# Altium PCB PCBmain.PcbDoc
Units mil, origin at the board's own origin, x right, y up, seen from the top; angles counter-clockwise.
Board outline 3224.41 x 4480.32 mil, 2 copper layers (Top Layer, Bottom Layer); 64 components, 75 nets, 222 pads, 65 vias.
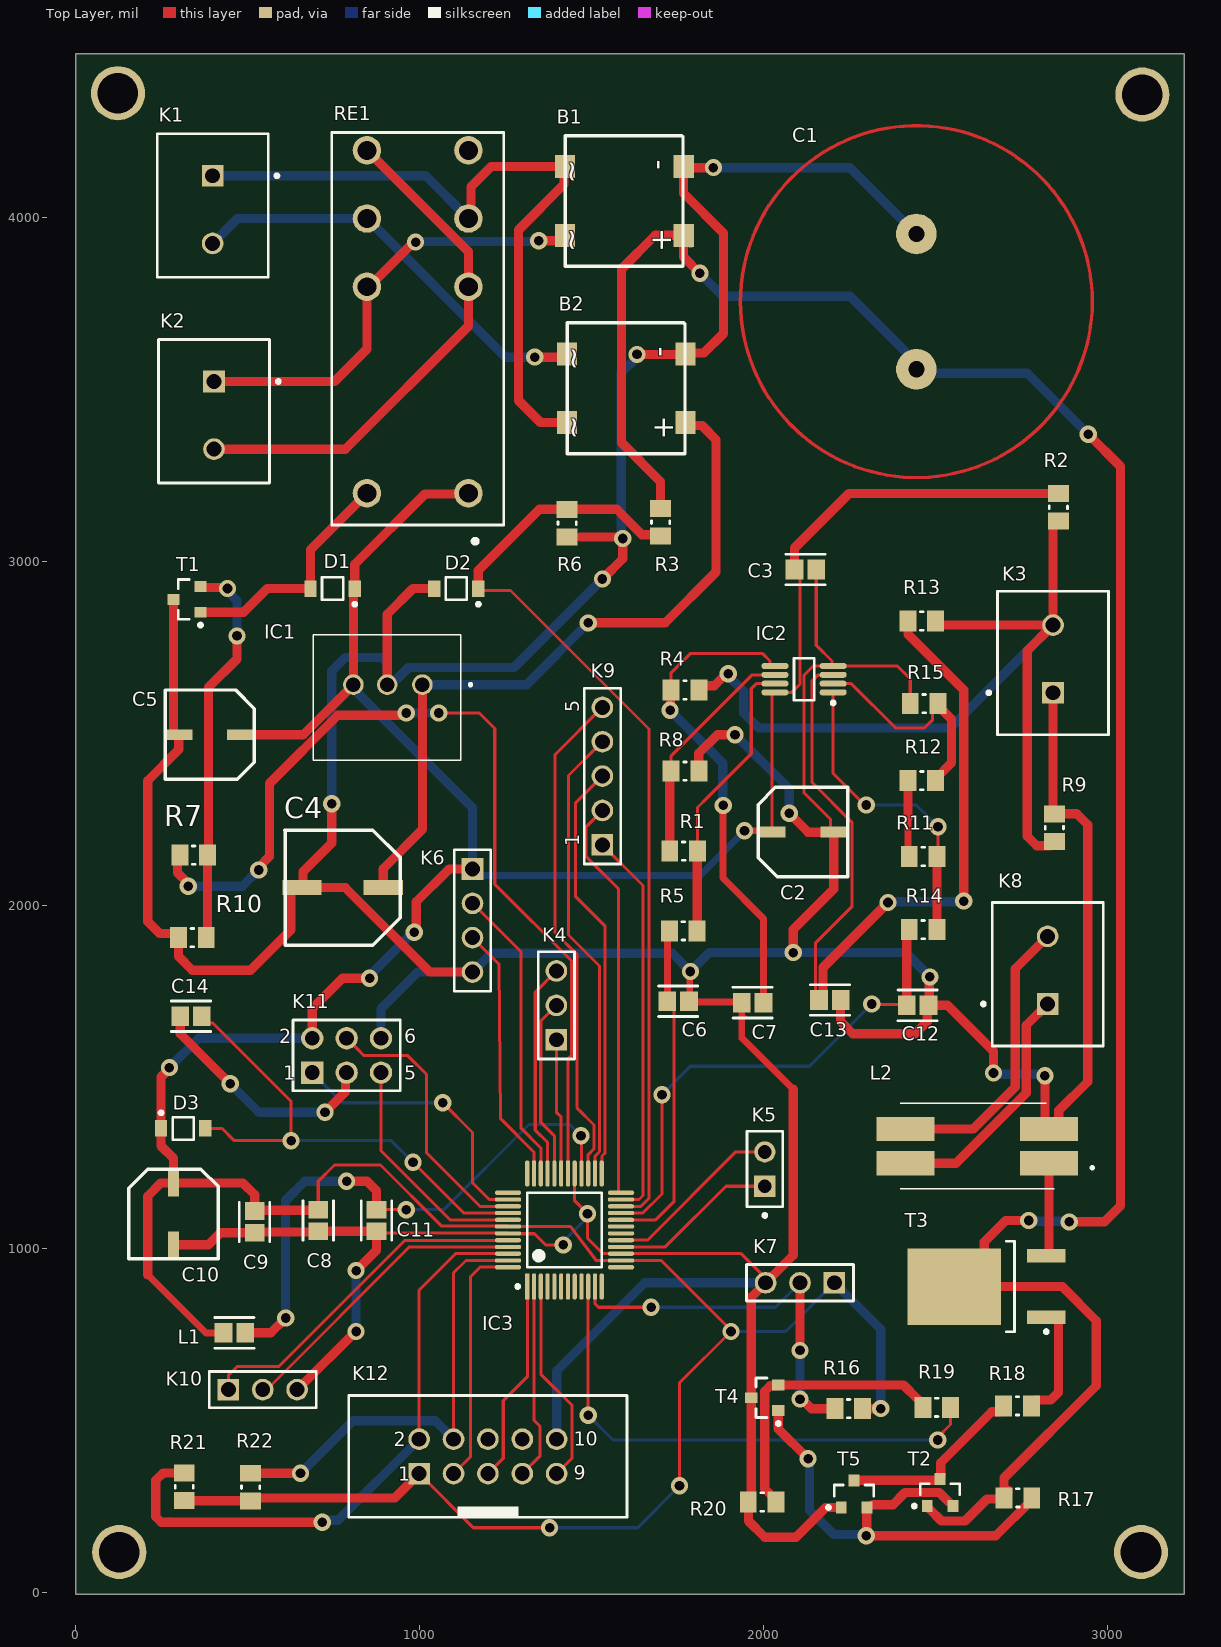
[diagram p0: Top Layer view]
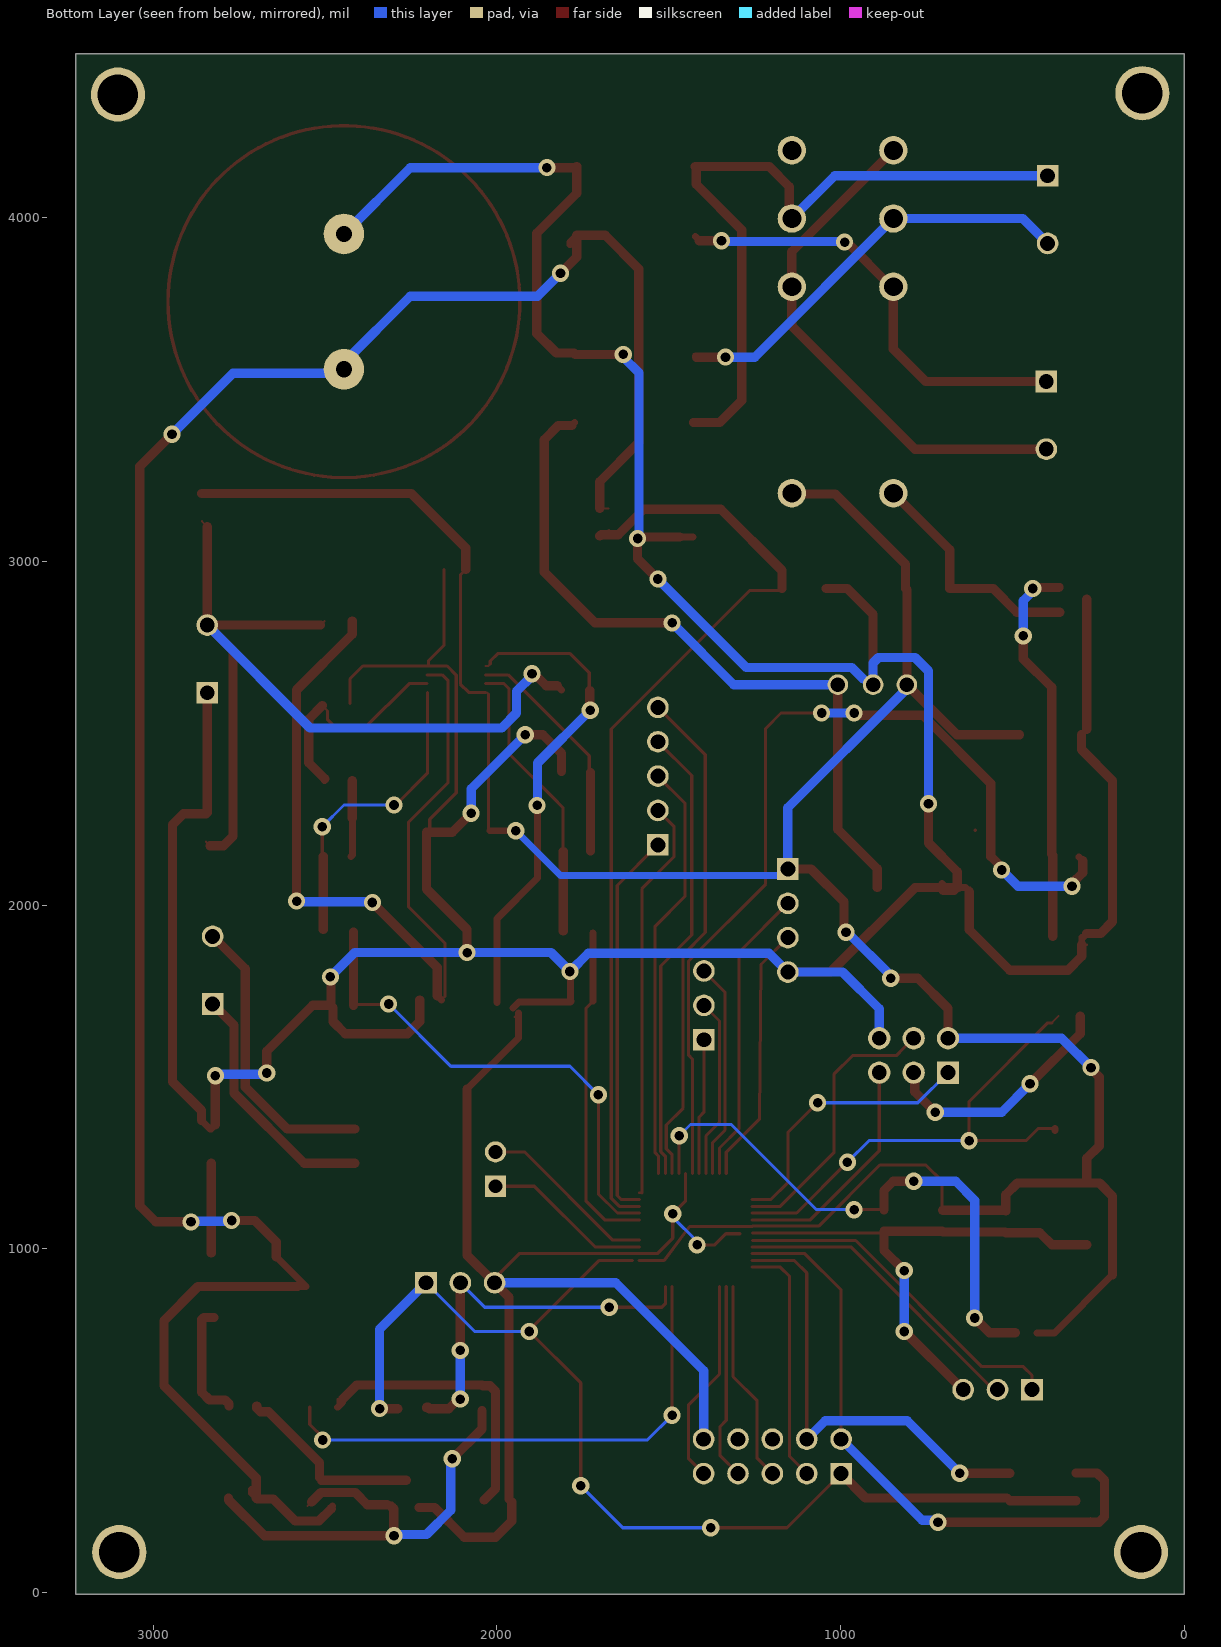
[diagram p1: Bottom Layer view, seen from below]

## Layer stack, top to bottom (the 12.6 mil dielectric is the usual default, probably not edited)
Top Solder: solder mask 0.4, Solder Resist, Dk 3.5
Top Layer: signal copper 1.4
Dielectric 1: dielectric 12.6, FR-4, Dk 4.8
Bottom Layer: signal copper 1.4
Bottom Solder: solder mask 0.4, Solder Resist, Dk 3.5

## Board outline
0,-3.94 3224.41,-3.94 3224.41,4476.38 0,4476.38

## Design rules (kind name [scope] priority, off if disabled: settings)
Clearance [All] p1: gap=2 ignorepadtopadclearanceinfootprint=TRUE except(0: Arc-Hole Track-Hole SMDPad-Hole THPad-Hole Via-Hole Fill-Hole Poly-Hole Region-Hole Text-Hole)
HoleSize [All] p1: absolutevalues=TRUE maxlimit=157.48 minlimit=0.98 maxpercent=80.000 minpercent=20.000
MinimumSolderMaskSliver [All] p1: minsoldermaskwidth=2
PolygonConnect [All] p1: connectstyle=Relief reliefconductorwidth=10 reliefentries=4 polygonreliefangle="90 Angle" airgapwidth=10
RoutingVias [All] p1: holewidth=28 width=50 viastyle="Through Hole" minholewidth=28 minwidth=50 maxholewidth=28 maxwidth=50
SilkToSilkClearance [All] p1: silktosilkclearance=2
SilkToSolderMaskClearance [IsPad] p1: minsilkscreentomaskgap=0 clearancetoexposedcopper=TRUE
SolderMaskExpansion [All] p1: expansion=4 istentingtop=FALSE
Width [All] p1: maxlimit=27 minlimit=6 preferedwidth=20 minimp=50.000000 maximp=50.000000 favimp=50.000000
26 further rules are at their usual default settings.

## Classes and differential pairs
component class voeding: B1 B2 C1 C4 C5 D1 D2 IC1 K1 K2 R3 R6 R7 R10 RE1 T1
component class thermokoppel: C2 C3 C6 C7 C12 C13 IC2 K3 R1 R2 R4 R5 R8 R9 R11 R12 R13 R14 R15
component class PWM: K8 L2 R17 R18 R19 R20 T2 T3 T4 T5
component class CPU: C8 C9 C10 C11 C14 D3 IC3 K4 K5 K6 K7 K9 K10 K11 L1 R16 R21 R22

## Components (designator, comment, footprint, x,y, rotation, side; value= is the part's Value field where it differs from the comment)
B1 "Bridge Rectifier" "ttf (bridge rectifier)" 1592.72,4048.82 r270 top
B2 "Bridge Rectifier" "ttf (bridge rectifier)" 1598.43,3503.94 r270 top
C1 "4700µ" C470µ 2444.88,3755.91 r270 top
C2 "10µ" "CE_D6,3_L4,5 (capacitor electrolytic)" 2114.72,2212.6 r180 top
C3 "100n" "CC_0805_L (choke/capacitor)" 2122.05,2976.38 r0 top value="0.22 μF"
C4 "100µ" CE_D8_L10 775.59,2051.18 r0 top
C5 "10µ" "CE_D6,3_L4,5 (capacitor electrolytic)" 389.21,2496.06 r0 top
C6 "10n" "CC_0805_L (choke/capacitor)" 1751.97,1720.47 r180 top value="0.22 μF"
C7 "10n" "CC_0805_L (choke/capacitor)" 1968.53,1716.53 r0 top value="0.22 μF"
C8 "100n" "CC_0805_L (choke/capacitor)" 704.72,1082.68 r270 top value="0.22 μF"
C9 "100n" "CC_0805_L (choke/capacitor)" 519.68,1078.74 r270 top value="0.22 μF"
C10 "10µ" "CE_D6,3_L4,5 (capacitor electrolytic)" 283.46,1101.81 r90 top
C11 "100n" "CC_0805_L (choke/capacitor)" 874.02,1082.68 r270 top value="0.22 μF"
C12 "10n" "CC_0805_L (choke/capacitor)" 2448.82,1708.66 r180 top value="0.22 μF"
C13 "10n" "CC_0805_L (choke/capacitor)" 2192.95,1724.41 r180 top value="0.22 μF"
C14 "100n" "CC_0805_L (choke/capacitor)" 334.68,1677.16 r180 top value="0.22 μF"
D1 "Diode" "SOD-123FL (diode)" 746.65,2921.26 r180 top value=15pF
D2 "5V1" "SOD-123FL (diode)" 1106.3,2921.26 r180 top value=15pF
D3 "Diode" "SOD-123FL (diode)" 311.95,1350.39 r0 top value=15pF
IC1 "OKI-78SR-5/1.5-W36-C" "OKI78SR515W36C ( DC/DC Converter)" 1007.87,2641.73 r180 top
IC2 "" "MSOP_8_L (dual opamp)" 2118.11,2657.48 r180 top
IC3 "ATMEGA4809" "TQFP_48_L (atmega)" 1421.26,1055.12 r90 top
K1 "282836-2" terminal_block 397.64,4023.62 r270 top
K2 "282836-2" terminal_block 401.57,3425.2 r270 top
K3 "" terminal_block 2842.52,2716.54 r90 top
K4 "61300311121" "pin header 1x3" 1397.64,1708.66 r90 top
K5 "M20-9990246" "pin header 1x2" 2003.94,1232.28 r90 top
K6 "61300411121" "pin header 1x4" 1153.54,1955.51 r270 top
K7 "61300311121" "pin header 1x3" 2106.3,901.57 r180 top
K8 "282836-2" terminal_block 2826.77,1811.03 r90 top
K9 "61300511121" "pin header 1x5" 1531.5,2375.59 r90 top
K10 "61300311121" "pin header 1x3" 543.31,590.55 r0 top
K11 "61300621121" "pin header 2x6" 787.4,1562.99 r0 top
K12 "61201021621" "box header 10-pin" 1198.42,396.46 r0 top
L1 "10µH" "CC_0805_L (choke/capacitor)" 460.63,755.91 r180 top
L2 "" "2545 (common mode choke)" 2622.05,1299.21 r90 top
R1 "18k" R_0805_L 1767.72,2157.48 r180 top
R2 "1M" R_0805_L 2858.27,3157.48 r270 top
R3 "68k" R_0805_L 1700.79,3114.17 r90 top
R4 "5k6" R_0805_L 1771.65,2625.98 r0 top
R5 "5k6" R_0805_L 1766.73,1925.2 r0 top
R6 "10k" R_0805_L 1429.13,3111.22 r90 top
R7 "10k" R_0805_L 342.52,2145.67 r0 top
R8 "100" R_0805_L 1771.65,2389.76 r180 top
R9 "10M" R_0805_L 2846.46,2225.4 r90 top
R10 "4k7" R_0805_L 338.58,1905.51 r0 top
R11 "18k" R_0805_L 2464.57,2141.73 r0 top
R12 "18k" R_0805_L 2460.63,2362.2 r0 top
R13 "5k6" R_0805_L 2460.63,2826.77 r0 top
R14 "5k6" R_0805_L 2464.57,1929.13 r180 top
R15 "100" R_0805_L 2467.52,2586.61 r0 top
R16 "4k7" R_0805_L 2248.03,535.43 r0 top
R17 "4k7" R_0805_L 2740.16,275.59 r180 top
R18 "100" R_0805_L 2739.17,543.31 r180 top
R19 "10k" R_0805_L 2503.94,539.37 r0 top
R20 "4k7" R_0805_L 1996.06,263.78 r0 top
R21 "4k7" R_0805_L 314.96,308.07 r270 top
R22 "4k7" R_0805_L 507.87,307.09 r270 top
RE1 "Relay general purpose" "RT42 (relay general p)" 994.09,3198.43 r90 top
T1 "" "SOT_23 (transistors)" 322.83,2889.76 r180 top
T2 "" "SOT_23 (transistors)" 2513.78,291.34 r90 top
T3 "" "TO_252 (mosfet)" 2649.6,890.55 r180 top
T4 "" "SOT_23 (transistors)" 2003.94,566.93 r180 top
T5 "" "SOT_23 (transistors)" 2263.78,287.4 r90 top

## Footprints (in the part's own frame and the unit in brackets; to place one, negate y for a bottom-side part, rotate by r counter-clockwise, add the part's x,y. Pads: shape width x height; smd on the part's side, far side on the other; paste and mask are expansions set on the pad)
"2545 (common mode choke)" [mm]
  rect 1.78x4.27 smd: 1(-1.27,-5.305) 2(1.27,-5.305) 3(1.27,5.305) 4(-1.27,5.305)
  silkscreen extent -3.15,-8.6 3.15,5.69, body extent -3.15,-7.26 3.15,7.26, height 9.6
"box header 10-pin" [mm] "10 pins, straight, gold plating"
  rect 1.6x1.6 hole 1.1: 1(-5.08,-1.27)
  round 1.6 hole 1.1: 2(-5.08,1.27) 3(-2.54,-1.27) 4(-2.54,1.27) 5(0,-1.27) 6(0,1.27) 7(2.54,-1.27) 8(2.54,1.27) 9(5.08,-1.27) 10(5.08,1.27)
  silkscreen extent -10.28,-4.5 10.28,4.5, body extent -10.18,-4.42 10.18,4.75, height 9.13
C470µ [mm]
  round 3 hole 1.2: 1(-5,0) 2(5,0)
  Top Layer circle w0.254: c0,0 r13
"CC_0805_L (choke/capacitor)" [mil]
  rect 51.36x57.33 smd paste+0 mask+0: 1(-31.53,0) 2(31.53,0)
  silkscreen extent -57,-44 57,44, body extent -67,-39 67,39, height 10
"CE_D6,3_L4,5 (capacitor electrolytic)" [mm]
  rect 2x0.8 smd: 1(-2.286,0) 2(2.286,0)
  silkscreen extent -3.3,-3.3 3.3,3.3
CE_D8_L10 [mm]
  rect 2.9x1.1 smd: 1(-3,0) 2(3,0)
  Top Layer lines w0.254: -4.259,4.25 -4.25,4.241
  silkscreen extent -4.26,-4.25 4.25,4.25
"MSOP_8_L (dual opamp)" [mm] "TSOP, 8-Leads, Body 3x3mm, Pitch 0.65mm, IPC Low Density"
  oval 2x0.45 smd: 1(-2.15,0.975) 2(-2.15,0.325) 3(-2.15,-0.325) 4(-2.15,-0.975) 5(2.15,-0.975) 6(2.15,-0.325) 7(2.15,0.325) 8(2.15,0.975)
  silkscreen extent -2.27,-1.55 0.75,1.87, body extent -1.55,-1.55 1.55,1.55, height 1.1
"OKI78SR515W36C ( DC/DC Converter)" [mm]
  round 1.519 hole 1.08: 1(0,0) 2(2.6,0) 3(5.1,0)
  silkscreen extent -3.6,-3.7 8.05,5.6, body extent -2.85,-3.7 8.05,5.6, height 16.6
"pin header 1x2" [mm]
  rect 1.57x1.57 hole 1.02 paste-1000 mask+0: 1(-1.27,0)
  round 1.57 hole 1.02 paste-1000 mask+0: 2(1.27,0)
  silkscreen extent -3.55,-1.32 2.79,1.32, body extent -2.89,-1.42 2.89,1.42, height 0.25
"pin header 1x3" [mm] "Pin Header, pitch 2.54 mm, THT, Vertical, single row, 3p"
  rect 1.6x1.6 hole 1.1: 1(-2.54,0)
  round 1.6 hole 1.1: 2(0,0) 3(2.54,0)
  silkscreen extent -3.96,-1.34 3.96,1.34, body extent -3.81,-1.27 3.81,1.27, height 8.57
"pin header 1x4" [mm] "Pin Header, pitch 2.54 mm, THT, Vertical, single row, 4p"
  rect 1.6x1.6 hole 1.1: 1(-3.81,0)
  round 1.6 hole 1.1: 2(-1.27,0) 3(1.27,0) 4(3.81,0)
  silkscreen extent -5.23,-1.35 5.23,1.35, body extent -5.08,-1.27 5.08,1.27, height 8.57
"pin header 1x5" [mm] "Pin Header, pitch 2.54 mm, THT, Vertical, single row, 5p"
  rect 1.6x1.6 hole 1.1: 1(-5.08,0)
  round 1.6 hole 1.1: 2(-2.54,0) 3(0,0) 4(2.54,0) 5(5.08,0)
  silkscreen extent -6.5,-1.34 6.5,1.35, body extent -6.35,-1.27 6.35,1.27, height 8.57
"pin header 2x6" [mm] "Pin Header, pitch 2.54 mm, THT, Vertical, dual row, 6p"
  rect 1.65x1.65 hole 1.1: 1(-2.54,-1.27)
  round 1.65 hole 1.1: 2(-2.54,1.27) 3(0,-1.27) 4(0,1.27) 5(2.54,-1.27) 6(2.54,1.27)
  silkscreen extent -3.96,-2.62 3.96,2.61, body extent -3.81,-2.54 3.81,2.54, height 8.59
R_0805_L [mm] "Chip Resistor, 2-Leads, Body 2.00x1.25mm, IPC Low Density"
  rect 1.25x1.55 smd: 1(-1.025,0) 2(1.025,0)
  silkscreen extent -0.1,-0.68 0.1,0.67, body extent -1.1,-0.72 1.1,0.72, height 0.5
"RT42 (relay general p)" [mm]
  round 2.1 hole 1.4: 1(0,-3.75) 2(15.26,-3.75) 3(20.3,-3.75) 4(25.34,-3.75) 5(25.34,3.75) 6(20.3,3.75) 7(15.26,3.75) 8(0,3.75)
  silkscreen extent -3.67,-6.35 26.65,6.35, body extent -2.21,-6.35 26.79,6.35, height 15.86
"SOD-123FL (diode)" [mm] "SOD, 2-Leads, Body 2.7x1.65mm"
  rect 0.91x1.22 smd: 1(-1.635,0) 2(1.635,0)
  silkscreen extent -1.76,-0.83 0.78,1.28, body extent -1.35,-0.82 1.35,0.82, height 1
"SOT_23 (transistors)" [mm] "SOT23, 3-Leads, Body 2.92x1.3mm, Pitch 0.95mm"
  rect 0.9x0.8 smd: 1(-1,0.95) 2(-1,-0.95) 3(1,0)
  silkscreen extent -1.13,-1.46 0.65,2.02, body extent -0.65,-1.46 0.65,1.46, height 1.11
terminal_block [mm] "Female Header, Pitch 5mm, 1 x 2 Position, Height 10mm"
  rect 1.6x1.6 hole 1.1: 1(-2.5,0)
  round 1.6 hole 1.1: 2(2.5,0)
  silkscreen extent -5.6,-4.1 5,4.88, body extent -5.6,-4.1 5,4.1, height 10
"TO_252 (mosfet)" [mm] "DPAK, 3-Leads, Body 6.5x6.12mm, Pitch 2.28mm, IPC Low Density"
  rect 2.85x1 smd: 1(-4.4,2.28) 3(-4.4,-2.28)
  rect 6.9x5.65 smd: 2(2.4,0)
  silkscreen extent -4.53,-3.35 -1.45,3.45, body extent -2.05,-3.32 4.17,3.32, height 2.35
"TQFP_48_L (atmega)" [mm]
  rect 1.955x0.312 smd paste+0 mask+0: 1(-4.175,2.75)
  rrect100% 1.955x0.312 smd paste+0 mask+0: 2(-4.175,2.25) 3(-4.175,1.75) 4(-4.175,1.25) 5(-4.175,0.75) 6(-4.175,0.25) 7(-4.175,-0.25) 8(-4.175,-0.75) 9(-4.175,-1.25) 10(-4.175,-1.75) 11(-4.175,-2.25) 12(-4.175,-2.75) 25(4.176,-2.75) 26(4.176,-2.25) 27(4.176,-1.75) 28(4.176,-1.25) 29(4.176,-0.75) 30(4.176,-0.25) 31(4.176,0.25) 32(4.176,0.75) 33(4.176,1.25) 34(4.176,1.75) 35(4.176,2.25) 36(4.176,2.75)
  rrect100% 0.312x1.955 smd paste+0 mask+0: 13(-2.75,-4.175) 14(-2.25,-4.175) 15(-1.75,-4.175) 16(-1.25,-4.175) 17(-0.75,-4.175) 18(-0.25,-4.175) 19(0.25,-4.175) 20(0.75,-4.175) 21(1.25,-4.175) 22(1.75,-4.175) 23(2.25,-4.175) 24(2.75,-4.175) 37(2.75,4.175) 38(2.25,4.175) 39(1.75,4.175) 40(1.25,4.175) 41(0.75,4.175) 42(0.25,4.175) 43(-0.25,4.175) 44(-0.75,4.175) 45(-1.25,4.175) 46(-1.75,4.175) 47(-2.25,4.175) 48(-2.75,4.175)
  silkscreen extent -4.3,-2.75 2.75,3.58, body extent -5.65,-5.65 5.65,5.65, height 0.25
"ttf (bridge rectifier)" [mm]
  rect 1.7x1.5 smd: 1(2.54,4.445) 2(-2.54,4.445) 3(-2.54,-4.318) 4(2.54,-4.318)
  silkscreen extent -4.83,-4.3 4.83,4.4

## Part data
B1 B2: Average Rectified Current-Max=0.8A, Forward Voltage=1V, Manufacturer="Diodes Inc", Package Description="4-Pin Small Outline Integrated Circuit, Body 4.7 x 3.8 mm, Pitch 2.5 mm", Package Reference=MiniDIP-4, Package Version=05/2016, Peak Current-Max=30A, Reverse Current-Max=5µA, Reverse Voltage-Max [Vrrm]=600V
C1 C2 C4 C5 C10: library part "Capacitor (electrolytic)", Manufacturer=Panasonic, Max Operating Temperature="105 degC", Min Operating Temperature="-55 degC", Package Quantity=500, Voltage Rating="25 V"
C3 C6 C7 C8 C9 C11 C12 C13 C14: library part "Capacitor (ceramic)", Capacitance="0.22 μF", Manufacturer=KEMET, Manufacturer Part Number=C0805C224K5RACTU, Package=C0805C-DN, Temperature="-55°C to +125°C", Temperature Characteristic=X7R, Temperature Coefficient=30ppm/°C, Temperature Range High=+125°C, Temperature Range Low=-55°C, Tolerance=0.1, Voltage Rating="50 V"
D1 D3: Capacitance=15pF, Forward Current=1A, Manufacturer=Diotec, Manufacturer Part Number=1N4007, Max Junction Temp=+175°C, Max Repetitive Reverse Voltage=1000V, Max Surge Forward Current=27A, Peak Reverse Current=5uA, Temperature="-50°C to +175°C", Temperature Range Low=-50°C
D2: library part "Zener diode", Capacitance=15pF, Forward Current=1A, Manufacturer=Diotec, Manufacturer Part Number=1N4007, Max Junction Temp=+175°C, Max Repetitive Reverse Voltage=1000V, Max Surge Forward Current=27A, Peak Reverse Current=5uA, Temperature="-50°C to +175°C", Temperature Range Low=-50°C
IC1: library part "DC/DC Converter", Current - Output (Max)=1.5A, Manufacturer=Murata, Operating Temperature=-40degC~85degC, Package / Case=3-SIPModule, Power (Watts) - Manufacture Series=8W, Voltage - Input (Max)=36V, Voltage - Input (Min)=7V, Voltage - Isolation=-, Voltage - Output 1=5V
IC2: library part "Dual Opamp", Case/Package=PDIP, Input Bias Current=1pA, Input Offset Voltage (Vos)=4.5mV, Max Operating Temperature=125°C, Max Supply Voltage=6V, Min Operating Temperature=-40°C, Min Supply Voltage=1.8V, Nominal Supply Current=100uA, Operating Supply Voltage=5.5V, Output Current=23mA, Package Quantity=60, Power Supply Rejection Ratio (PSRR)=86dB, Voltage Gain=112dB
IC3: Case/Package=TQFP, Max Operating Temperature=85°C, Min Operating Temperature=-40°C
K1 K2 K3 K8: library part "terminal block", "Female Header, Pitch 5 mm, 1 x 2 Position, Height 10 mm, Tail Length 3.5 mm, Rohs, Bulk", Color=Green, Current=13.5A, Manufacturer="TE Connectivity", Package Description="Female Header, Pitch 5 mm, 1 x 2 Position, Height 10 mm, Tail Length 3.5 mm", Package Reference=THD, Standard Package=300, Voltage=300V
K4 K7 K10: library part "pin header 1x3pin", "THT Vertical Pin Header WR-PHD, Pitch 2.54 mm, Single Row, 3 pins", Contact Resistance=20mOhm, Manufacturer="Wurth Elektronik", Operating Temperature=-40to105degC, Rated Current=3A, Withstanding Voltage=500VAC, Working Voltage=250VAC
K5: library part "pin header 1x2", "CONN HEADER VERT 2POS 2.54MM", Current Rating=3A, Manufacturer=Harwin, Temperature="-40°C to +105°C", Temperature Range High=+105°C, Temperature Range Low=-40°C
K6: library part "pin header 1x4", "THT Vertical Pin Header WR-PHD, Pitch 2.54 mm, Single Row, 4 pins", Contact Resistance=20mOhm, Manufacturer="Wurth Elektronik", Operating Temperature=-40to105degC, Rated Current=3A, Withstanding Voltage=500VAC, Working Voltage=250VAC
K9: library part "pin header 1x5", "THT Vertical Pin Header WR-PHD, Pitch 2.54 mm, Single Row, 5 pins", Contact Resistance=20mOhm, Manufacturer="Wurth Elektronik", Operating Temperature=-40to105degC, Rated Current=3A, Withstanding Voltage=500VAC, Working Voltage=250VAC
K11: library part "pin header 2x6", "THT Vertical Pin Header WR-PHD, Pitch 2.54 mm, Dual Row, 6 pins", Contact Resistance=20mOhm, Manufacturer="Wurth Elektronik", Operating Temperature=-40to105degC, Rated Current=3A, Withstanding Voltage=500VAC, Working Voltage=250VAC
K12: library part "Box Header", "Male Box Header WR-BHD, THT, Vertical, pitch 2.54 mm, 10 pins", Contact Resistance=20mOhm, Manufacturer="Wurth Elektronik", Operating Temperature=-40to125degC, Withstanding Voltage=500VAC, Working Voltage=250VAC
L1: library part Choke, Case/Package=1350, Current Rating=8.5A, DC Resistance (DCR)=14.1mR, Inductance=10uH, Inductance Tolerance=20%, Max Operating Temperature=155°C, Min Operating Temperature=-40°C, Package Quantity=1, Ratings=AEC-Q200, Resistor Type=Wirewound, Saturation Current=10A, Self Resonant Frequency=18MHz, Series Resistance=14.1R, Test Frequency=100kHz
L2: library part "Common Mode Choke", Case/Package=1808, Current=2A, Current Rating=2.3A, DC Resistance (DCR)=60mR, Insulation Resistance=10MR, Max Operating Temperature=85°C, Max Voltage Rating (DC)=50V, Min Operating Temperature=-40°C, Package Quantity=1, Test Frequency=100MHz
R1 R2 R3 R4 R5 R6 R7 R8 R9 R10 R11 R12 R13 R14 R15 R16 R17 R18 R19 R20 R21 R22: library part Resistor, Manufacturer="Vishay Dale", Part Number=CRCW08050000Z0EA
RE1: Ambient Temperature Range High=+85°C, Ambient Temperature Range Low=-40°C, Coil Power=403mW, Coil Resistance=62Ω, Coil Voltage=5V, Current Rating=8A, Manufacturer="TE Connectivity", Manufacturer Part Number=RT424005
T1 T2 T4: library part "Transistor NPN", Manufacturer="On Semiconductor", PartNumber=BC547C
T3: library part Mosfet, Continuous Drain Current Id=2.4A, Current Temperature=25°C, Drain Source Voltage Vds=20V, Manufacturer="Fairchild Semiconductor", On Resistance Rds(on)=52mohm, Operating Temperature Max=150°C, Operating Temperature Min=-55°C, Operating Temperature Range=-55°Cto+150°C, Package / Case=SOT-23, Package Description="3-Pin Small Outline Transistor, Body 2.92 x 1.4 mm, Pitch 0.95 mm", Package Reference=SSOT3L, Package Version="Rev. 3, 05/2015", Power Dissipation Pd=500mW, Pulse Current Idm=10A, Rds(on) Test Voltage Vgs=-4.5V, Threshold Voltage Vgs Typ=-800mV, Voltage Vds Typ=-20V, Voltage Vgs th Max=-1.5V
T5: library part "Transistor PNP", Manufacturer="On Semiconductor", PartNumber=BC557C

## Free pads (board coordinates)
  round 157.48 hole 118.11: 2(125.98,118.11) 3(3098.43,118.11) 4(3102.36,4358.27) 5(122.05,4362.2)

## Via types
v1: diameter 50, hole 28, Top Layer to Bottom Layer, 65 vias

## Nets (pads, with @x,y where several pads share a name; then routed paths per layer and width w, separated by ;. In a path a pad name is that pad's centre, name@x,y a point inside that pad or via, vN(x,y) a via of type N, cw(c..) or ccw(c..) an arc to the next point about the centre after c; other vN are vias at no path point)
+5: C2.2 C3.1 C5.2 C8.1 C9.1 C10.2 D1.1 D3.1 IC1.3 IC2.8 IC3.14 IC3.42 K6.1 K7.1 K11.2 K12.1 L1.2 R2.1 R16.2 R21.2 R22.2 RE1.1 | length 11664.1
  Top Layer w6: 410.17,267.72 411.16,266.73 ; D1.1@807.09,2917.32 D1.1 D1.1@811.02,2924.43 ; IC3.42@1255.67,1066.17 IC3.42 ; 1438.94,1064.96 1441.35,1062.56 ; 1511.59,968.6 1511.89,968.3 1513.65,966.54 ; v1(1905.51,759.84) v1@1905.51,763.78 ; C2.2@2020.79,2216.54 C2.2 ; IC2.8@2024.73,2613.68 2030.14,2619.1 IC2.8
  Top Layer w9: C8.1 704.72,1196.85 751.97,1244.09 885.83,1244.09 1063.75,1066.17 IC3.42@1255.67,1066.17 ; K12.1 1155.91,188.98 v1(1377.95,188.98) ; IC3.42 1438.94,1064.96 ; 1441.35,1062.56 1511.59,968.6 ; 1513.65,966.54 IC3.14 ; IC3.14@1605.4,966 1703.29,966 v1@1905.51,763.78 ; v1(1755.91,311.02) 1755.91,610.24 v1(1905.51,759.84) ; C2.2 IC2.8@2024.73,2613.68 ; IC2.8 2082.17,2619.1 2106.3,2643.22 2106.3,2960.6 C3.1
  Top Layer w20: 208.66,925.2 377.95,755.91 L1.2 ; R22.2 R22.2@516.73,275.59 ; C9.1 C9.1@521.65,1112.23 ; K11.2 K11.2@687.4,1616.73 ; C8.1@702.76,1112.23 C8.1 ; D1.1@811.02,2924.43 D1.1@811.02,2927.36 ; v1@854.33,1783.66 v1(854.33,1787.4) ; v1(984.25,1921.26) v1@989.99,1927 ; RE1.1@1139.64,3196.34 RE1.1 ; v1(1944.88,2216.54) C2.2@2020.79,2216.54
  Top Layer w27: 208.66,925.2 208.66,1153.54 246.93,1191.81 C10.2 ; v1(271.65,1527.56) 271.65,1524.31 247.58,1500.24 247.58,1299.66 283.46,1263.78 C10.2 ; R21.2 410.17,267.72 R22.2@506.89,267.72 ; C5.2 661.42,2496.06 IC1.3 D1.1@807.09,2917.32 ; R22.2@516.73,275.59 927.56,275.59 K12.1 ; C9.1 519.68,1157.48 485.35,1191.81 C10.2 ; C9.1@521.65,1112.23 C8.1@702.76,1112.23 ; K11.2 687.4,1699.21 775.59,1787.4 v1(854.33,1787.4) ; D1.1 811.02,2935.28 811.02,2992.13 1015.23,3196.34 RE1.1@1139.64,3196.34 ; v1@989.99,1927 989.99,2009.68 1085.83,2105.51 K6.1 ; C3.1 2090.52,3039.43 2248.93,3197.84 R2.1 ; R16.2 v1(2341.17,535.44)
  Bottom Layer w6: IC1.3 816.78,2632.04 IC1.3@816.78,2620.22 ; K12.1 K12.1@1026.92,374.95 ; K6.1 K6.1@1172.44,2086.61
  Bottom Layer w9: v1(1377.95,188.98) 1633.86,188.98 v1(1755.91,311.02) ; v1(1905.51,759.84) 2064.57,759.84 K7.1
  Bottom Layer w20: v1(854.33,1787.4) v1@854.33,1795.28 ; v1@980.31,1921.26 v1(984.25,1921.26) ; K6.1@1172.44,2086.61 1814.96,2086.61 v1(1944.88,2216.54)
  Bottom Layer w27: v1(271.65,1527.56) 357.09,1612.99 K11.2 ; IC1.3@816.78,2620.22 1153.54,2283.46 K6.1 ; v1@854.33,1795.28 v1@980.31,1921.26 ; K7.1 2341.17,766.7 v1(2341.17,535.44)
GND: B1.2 B2.2 C1.1 C2.1 C3.2 C4.1 C5.1 C6.1 C7.1 C8.2 C9.2 C10.1 C11.2 C12.1 C13.1 D2.2 IC1.2 IC2.4 IC3.15 IC3.29 IC3.43 K3.1 K6.4 K7.3 K10.3 K11.6 K12.10 L2.2 R6.1 R8.1 R9.2 R10.1 R15.1 R20.1 T1.3 T4.3 T5.1 | length 19125.6
  Top Layer w6: R10.1@283.47,1884.85 R10.1@298.23,1884.85 ; 283.46,2511.81 C5.1 ; C4.1@622.17,2051.18 C4.1@637.07,2051.18 ; K6.4@1144.09,1814.96 K6.4 ; IC3.43@1256,1046.15 IC3.43 ; IC3.43@1291.34,1044.85 IC3.43@1292.12,1044.07 ; 1467.56,3070.87 1473.82,3064.61 ; 1937.01,1686.59 1949.17,1674.43 ; R20.1 R20.1@1964.57,272.64 ; K7.3 K7.3@2006.3,914.96 ; C2.1@2195.3,2222.02 C2.1 ; IC2.4@2199.24,2699.38 IC2.4 ; R9.2@2842.52,2269.69 R9.2
  Top Layer w9: C11.2@874.86,1046.15 IC3.43@1256,1046.15 ; IC3.43@1292.12,1044.07 1333.88,1044.07 1366.14,1011.81 v1(1417.32,1011.81) ; IC3.29 1450.79,1139.76 v1(1488.19,1102.36) 1488.19,1031.5 1533.46,986.22 IC3.15 1935.04,986.22 K7.3@2006.3,914.96 ; C3.2 2153.57,2755.88 2199.24,2710.21 IC2.4@2199.24,2699.38 ; C2.1@2195.3,2222.02 2195.3,2249.58 2118.11,2326.77 2118.11,2669.29 2144.69,2695.87 2199.24,2695.87 IC2.4 2389.72,2695.87 2427.17,2658.43 R15.1
  Top Layer w20: R10.1@283.62,1917.89 298.23,1903.28 R10.1@298.23,1899.61 ; R10.1@298.23,1884.85 R10.1 ; C9.2 C9.2@521.65,1049.18 ; C4.1@625.42,2039.53 637.07,2051.18 C4.1 669.14,2039.53 C4.1@681.26,2039.53 ; K10.3@651.53,598.78 K10.3@652.72,598.78 ; C4.1@692.92,2051.18 C4.1@704.57,2062.83 ; C8.2@702.76,1049.18 C8.2 ; v1@813.78,759.84 v1(814.96,759.84) ; R6.1 1467.56,3070.87 ; v1@1586.61,3070.87 v1(1590.55,3066.93) ; B1.2 B1.2@1770.87,4145.67 ; B2.2@1771.85,3602.36 B2.2 B2.2@1773.43,3607.88 ; v1(1787.4,1807.09) 1785.45,1805.13 1785.45,1722.42 C6.1 1785.46,1718.5 1935.04,1718.5 C7.1 C7.1@1952.69,1700.85 ; 1937.01,1686.59 1937.01,1614.17 2086.61,1464.57 ; C12.1@2476.67,1702 2482.3,1707.63 2482.3,1708.66 C12.1 ; v1@2482.3,1789.38 v1(2484.25,1791.34) ; L2.2@2818.9,1361.22 L2.2 2834.19,1349.21 L2.2@2859.23,1374.25
  Top Layer w26: B2.2 B2.2@1775.74,3606.25
  Top Layer w27: C10.1 385.26,1011.81 420.66,1047.21 C9.2 ; 283.46,2511.81 T1.3 ; R10.1@283.62,1917.89 243.53,1917.89 208.66,1952.76 208.66,2362.2 299.21,2452.76 C5.1 ; R10.1@298.23,1884.85 298.23,1851.38 338.58,1811.02 507.87,1811.02 625.42,1928.57 C4.1@625.42,2039.53 ; C9.2@521.65,1049.18 C8.2@702.76,1049.18 ; K10.3@652.72,598.78 v1@813.78,759.84 ; C4.1 C4.1@669.14,2051.18 ; C4.1@660.51,2054.21 660.51,2097.52 744.09,2181.1 v1(744.09,2295.28) ; C4.1@701.07,2043.03 700.79,2043.31 685.04,2043.31 677.17,2051.18 C4.1@669.14,2051.18 ; C8.2 C11.2 874.02,996.06 v1(814.96,937.01) ; IC1.2 905.51,2846.46 980.32,2921.26 D2.2 ; K6.4 1029.13,1805.51 783.46,2051.18 704.57,2051.18 692.92,2051.18 681.26,2051.18 C4.1@669.14,2051.18 ; 1467.56,3070.87 v1@1586.61,3070.87 ; v1(1531.5,2948.82) 1590.55,3007.87 v1(1590.55,3066.93) ; v1(1632.17,3602.36) B2.2@1771.85,3602.36 ; B1.2 1767.72,4070.87 1883.58,3955 1883.58,3663.11 1826.72,3606.25 B2.2@1775.74,3606.25 ; B1.2@1770.87,4145.67 v1(1854.33,4145.67) ; R8.1 1812.01,2441.93 1866.14,2496.06 v1(1917.32,2496.06) ; R20.1 1956.77,262.72 1956.77,208.58 2003.94,161.42 2094.49,161.42 2181.1,248.03 T5.1 ; R20.1@1964.57,272.64 T4.3 1964.57,859.85 K7.3 2086.61,981.89 2086.61,1464.57 ; v1(2074.8,2267.72) 2129.92,2212.6 C2.1 2204.73,2047.24 2086.61,1929.13 v1(2086.61,1862.2) ; C13.1 2224.47,1661.36 2259.84,1625.98 2440.94,1625.98 2476.67,1661.71 C12.1@2476.67,1702 ; v1@2482.3,1789.38 2482.3,1708.66 2535.44,1708.66 2669.29,1574.8 v1(2669.29,1511.81) ; L2.2@2818.9,1361.22 v1(2818.9,1503.94) ; R9.2@2842.52,2269.69 K3.1 ; R9.2 2911.42,2265.75 2943.32,2233.84 2943.32,1486.63 2859.23,1402.54 L2.2@2859.23,1374.25
  Bottom Layer w6: v1(1417.32,1011.81) v1@1417.32,1021.65 ; v1@1488.19,1092.52 v1(1488.19,1102.36)
  Bottom Layer w9: v1@1417.32,1021.65 v1@1488.19,1092.52
  Bottom Layer w20: IC1.2 916.28,2641.73 932.51,2657.97 933.99,2657.97 ; v1@1586.61,3070.87 v1(1590.55,3066.93) ; v1@1632.17,3594.24 v1(1632.17,3602.36) ; v1(2669.29,1511.81) v1@2673.23,1507.87 ; v1@2814.96,1507.87 v1(2818.9,1503.94)
  Bottom Layer w27: v1(744.09,2295.28) 744.09,2681.1 783.46,2720.47 889.76,2720.47 905.51,2704.73 IC1.2 ; v1(814.96,759.84) v1(814.96,937.01) ; K11.6 887.4,1698.42 994.49,1805.51 K6.4 1208.19,1860.16 1734.33,1860.16 v1(1787.4,1807.09) 1842.52,1862.2 v1(2086.61,1862.2) 2413.39,1862.2 v1(2484.25,1791.34) ; 933.99,2657.97 967.66,2691.63 1274.31,2691.63 v1(1531.5,2948.82) ; K12.10 1398.43,645.68 1654.32,901.58 K7.3 ; v1@1586.61,3070.87 1586.61,3548.69 v1@1632.17,3594.24 ; v1(1854.33,4145.67) 2251.97,4145.67 C1.1 ; v1(1917.32,2496.06) 2074.8,2338.58 v1(2074.8,2267.72) ; v1@2673.23,1507.87 v1@2814.96,1507.87
NetB1_3: B1.3 B2.4 K1.1 RE1.3 | length 2093.2
  Top Layer w20: RE1.3 RE1.3@1149.34,4005.25 ; B1.3@1419.9,4146.01 B1.3
  Top Layer w26: B2.4@1427.96,3404.4 B2.4
  Top Layer w27: RE1.3@1149.34,4005.25 1149.34,4090.29 1207.87,4148.82 B1.3 ; B1.3@1419.9,4146.01 1419.9,4097.07 1287.4,3964.57 1287.4,3468.5 1351.51,3404.4 B2.4@1427.96,3404.4
  Bottom Layer w27: K1.1 1017.32,4122.05 RE1.3
NetB1_4: B1.4 K2.1 RE1.7 | length 1301.7
  Top Layer w20: RE1.7 RE1.7@852.36,3799.21 ; v1@982.28,3929.13 v1(988.19,3929.13) ; B1.4@1410.91,3933.07 B1.4@1422.72,3944.88
  Top Layer w27: K2.1 751.97,3523.62 846.46,3618.11 RE1.7 ; RE1.7@852.36,3799.21 v1@982.28,3929.13 ; v1(1346.46,3933.07) B1.4@1410.91,3933.07
  Bottom Layer w20: v1(988.19,3929.13) v1@990.16,3931.1 ; v1@1344.49,3931.1 v1(1346.46,3933.07)
  Bottom Layer w27: v1@990.16,3931.1 v1@1344.49,3931.1
NetB2_1: B2.1 C4.2 IC1.1 | length 2122.5
  Top Layer w6: IC1.1 IC1.1@1008.17,2641.73
  Top Layer w20: B2.1 B2.1@1782.07,3395.3
  Top Layer w27: C4.2 893.7,2106.3 1008.17,2220.77 IC1.1@1008.17,2641.73 ; v1(1490.17,2821.43) 1714.17,2821.43 1862.2,2969.46 1862.2,3354.33 1821.24,3395.3 B2.1@1782.07,3395.3
  Bottom Layer w27: IC1.1 1310.48,2641.73 v1(1490.17,2821.43)
NetB2_3: B2.3 K1.2 RE1.6 | length 1235.5
  Top Layer w6: B2.3@1421.73,3597.25 B2.3
  Top Layer w20: RE1.6@846.46,3993.79 RE1.6 ; B2.3@1418.97,3594.49 B2.3@1421.73,3597.25
  Top Layer w27: v1(1334.65,3594.49) B2.3@1418.97,3594.49
  Bottom Layer w27: K1.2 470.08,3997.64 RE1.6 1249.61,3594.49 v1(1334.65,3594.49)
NetC1(d)_2: 
NetC3(d)_2: 
NetC4(d)_2: 
NetC5(d)_2: 
NetC7_2: C7.2 IC2.5 R4.1 | length 1419.5
  Top Layer w6: IC2.5@2019.12,2701.28 2024.53,2695.87 IC2.5
  Top Layer w9: R4.1 1731.3,2676.18 1786.81,2731.69 1997.64,2731.69 2019.12,2710.21 IC2.5@2019.12,2701.28
  Top Layer w20: v1(1728.35,2566.93) v1@1729.82,2568.41 ; R4.1@1729.82,2624.51 R4.1 ; v1(1882.97,2290.27) 1881.89,2289.19 1881.89,2078.74 2000.06,1960.57 C7.2
  Top Layer w27: v1@1729.82,2568.41 R4.1@1729.82,2624.51
  Bottom Layer w27: v1(1728.35,2566.93) 1881.89,2413.39 1881.89,2291.35 v1(1882.97,2290.27)
NetC11_1: C11.1 IC3.28 L1.1 | length 1654.3
  Top Layer w6: v1(1469.17,1329.43) v1@1470.47,1328.13
  Top Layer w9: C11.1 v1(960.63,1114.17) ; IC3.28 v1@1470.47,1328.13
  Top Layer w27: L1.1 566.93,755.91 v1(610.24,799.21) ; v1(787.4,1196.85) 846.46,1196.85 874.02,1169.29 C11.1
  Bottom Layer w9: v1(960.63,1114.17) 1069.92,1114.17 1317.95,1362.2 1436.39,1362.2 v1(1469.17,1329.43)
  Bottom Layer w20: v1@609.33,800.12 v1(610.24,799.21)
  Bottom Layer w27: v1@609.33,800.12 609.33,1140.83 665.35,1196.85 v1(787.4,1196.85)
NetC13_2: C13.2 IC2.3 R13.1 | length 2563.8
  Top Layer w6: C13.2@2150.89,1734.94 C13.2
  Top Layer w9: C13.2@2150.89,1734.94 2150.89,1889.22 2257.1,1995.43 2257.1,2241.43 2141.73,2356.79 2141.73,2652.84 2159.17,2670.28 IC2.3
  Top Layer w20: C13.2 C13.2@2173.23,1736.22
  Top Layer w27: C13.2@2173.23,1736.22 2173.23,1818.9 v1(2362.2,2007.87) ; R13.1 2420.28,2788.38 2582.68,2625.98 v1(2582.68,2011.81)
  Bottom Layer w20: v1(2362.2,2007.87) v1@2364.17,2009.84 ; v1@2580.71,2009.84 v1(2582.68,2011.81)
  Bottom Layer w27: v1@2364.17,2009.84 v1@2580.71,2009.84
NetC14_1: C14.1 D3.2 IC3.40 | length 1465.3
  Top Layer w6: C14.1 C14.1@385.62,1657.75
  Top Layer w9: D3.2 425.2,1350.39 460.63,1314.96 v1(625.98,1314.96) 625.98,1429.13 397.37,1657.75 C14.1@385.62,1657.75 ; v1(980.31,1251.97) 1127.95,1104.33 IC3.40
  Top Layer w20: D3.2@376.32,1344.29 D3.2
  Bottom Layer w9: v1(625.98,1314.96) 917.32,1314.96 v1(980.31,1251.97)
NetC14_2: C14.2 K11.3 | length 708.5
  Top Layer w20: K11.3@784.19,1509.78 K11.3
  Top Layer w27: C14.2 303.15,1625.98 v1(448.82,1480.32) ; v1(724.41,1397.64) 784.19,1457.42 K11.3@784.19,1509.78
  Bottom Layer w27: v1(448.82,1480.32) 531.5,1397.64 v1(724.41,1397.64)
NetD1_2: D1.2 RE1.8 T1.1 | length 693.8
  Top Layer w27: T1.1 487.17,2852.36 556.07,2921.26 D1.2 682.28,3034.25 RE1.8
NetIC1(d)_2: 
NetIC1(d)_3: 
NetIC1(d)_4: 
NetIC1(d)_5: 
NetIC1(d)_6: 
NetIC1(d)_7: 
NetIC1(d)_8: 
NetIC1(d)_9: 
NetIC1(d)_12: 
NetIC1(d)_13: 
NetIC1(d)_14: 
NetIC1(d)_15: 
NetIC1(d)_17: 
NetIC1(d)_18: 
NetIC2_1: IC2.1 R11.2 R14.1 | length 908.7
  Top Layer w6: IC2.1@2202.17,2619.1 IC2.1 ; v1@2294.26,2291.34 v1(2299.21,2291.34) ; R11.2@2502.46,2144.19 R11.2@2507.87,2149.61
  Top Layer w9: IC2.1@2202.17,2619.1 2202.17,2383.43 v1@2294.26,2291.34 ; R11.2@2507.87,2149.61 v1(2507.87,2228.35)
  Top Layer w20: R11.2@2502.46,2144.19 R11.2
  Top Layer w27: R14.1 R11.2
  Bottom Layer w9: v1(2299.21,2291.34) 2444.88,2291.34 v1(2507.87,2228.35)
NetIC2_2: IC2.2 R12.2 R15.2 | length 654.4
  Top Layer w6: R15.2@2492.13,2564.96 R15.2@2507.87,2580.71
  Top Layer w9: IC2.2 2255.17,2644.69 2384.11,2515.75 2468.5,2515.75 2492.13,2539.37 R15.2@2492.13,2564.96
  Top Layer w20: R12.2 R12.2@2500.99,2368.11
  Top Layer w27: R12.2@2500.99,2368.11 2547.24,2414.37 2547.24,2541.34 R15.2@2507.87,2580.71
NetIC2_6: IC2.6 R1.2 R8.2 | length 678.5
  Top Layer w6: R8.2@1727.36,2385.83 R8.2
  Top Layer w9: R8.2 1731.3,2434.47 1967.1,2670.28 IC2.6
  Top Layer w27: R1.2 R8.2@1727.36,2385.83
NetIC2_7: IC2.7 R1.1 R5.2 | length 845
  Top Layer w6: 1807.09,2040.43 1808.07,2041.41
  Top Layer w9: R1.1 1808.07,2284.45 1836.09,2312.47 1964.57,2440.94 1964.57,2629.92 1979.33,2644.69 IC2.7
  Top Layer w27: R5.2 1807.09,2040.43 R1.1@1807.09,2156.5
NetIC3_1: IC3.1 K12.5 | length 591.7
  Top Layer w9: K12.5 1242.92,390.95 1242.92,558.43 1312.99,628.5 IC3.1
NetIC3_2: IC3.2 K12.7 | length 573.1
  Top Layer w9: K12.7 1350.39,398.43 1350.39,483.48 1332.68,501.2 IC3.2
NetIC3_3: IC3.3 K12.9 | length 600.2
  Top Layer w9: IC3.3 1352.36,635.83 1442.92,545.27 1442.92,390.95 K12.9
NetIC3_11: IC3.11 K7.2 R16.1 | length 1134.9
  Top Layer w9: IC3.11 1509.84,840.55 1519.97,830.43 v1(1673.17,830.43)
  Top Layer w20: R16.1@2203.74,539.37 R16.1
  Top Layer w27: v1(2106.3,562.99) 2112.52,562.99 2140.08,535.44 2196.57,535.44 2200.51,539.37 R16.1@2203.74,539.37 ; v1(2106.3,704.72) K7.2
  Bottom Layer w9: v1(1673.17,830.43) 2035.15,830.43 K7.2
  Bottom Layer w27: v1(2106.3,562.99) v1(2106.3,704.72)
NetIC3_16: IC3.16 K5.1 | length 491.3
  Top Layer w9: IC3.16 1714.57,1005.91 1890.94,1182.28 K5.1
NetIC3_17: IC3.17 K5.2 | length 524.6
  Top Layer w9: IC3.17 1662.71,1025.59 1919.4,1282.28 K5.2
NetIC3_23: IC3.23 K9.1 | length 1138
  Top Layer w9: K9.1 1649.61,2057.48 1649.61,1155.33 1637.98,1143.7 IC3.23
NetIC3_24: IC3.24 K9.2 | length 1178.2
  Top Layer w6: IC3.24@1578.17,1163.39 IC3.24
  Top Layer w9: K9.2 1484.25,2228.35 1484.25,2141.46 1494.61,2131.1 1578.17,2047.54 IC3.24@1578.17,1163.39
NetIC3_25: IC3.25 K9.3 | length 1228.6
  Top Layer w9: IC3.25 1530.16,1220.14 1530.16,1270.32 1539.37,1279.53 1539.37,1939.23 1452.76,2025.84 1452.76,2296.85 K9.3
NetIC3_26: IC3.26 K9.4 | length 1339.7
  Top Layer w9: IC3.26 1509.84,1269.69 1523.17,1283.02 1523.17,1823.01 1433.07,1913.11 1433.07,2377.17 K9.4
NetIC3_27: IC3.27 K9.5 | length 1467.2
  Top Layer w9: IC3.27 1490.16,1274.41 1507.17,1291.43 1507.17,1360.43 1458.13,1409.47 1458.13,1856.05 1393.7,1920.48 1393.7,2437.8 K9.5
NetIC3_31: IC3.31 K4.1 | length 394.9
  Top Layer w9: K4.1 1397.64,1397.64 1411.42,1383.86 IC3.31
NetIC3_32: IC3.32 K4.2 | length 524.4
  Top Layer w9: IC3.32 1391.73,1329.05 1352.17,1368.61 1352.17,1663.2 K4.2
NetIC3_33: IC3.33 K4.3 | length 629.5
  Top Layer w9: IC3.33 1372.05,1309.85 1336.17,1345.72 1336.17,1747.2 K4.3
NetIC3_34: IC3.34 K6.2 | length 868.4
  Top Layer w9: K6.2 1295.17,1863.88 1295.17,1351 1352.36,1293.81 IC3.34
NetIC3_35: IC3.35 K6.3 | length 758.5
  Top Layer w9: K6.3 1228.57,1830.48 1231.17,1827.88 1235.32,1378.86 1332.68,1281.5 IC3.35
NetIC3_38: IC3.38 K11.1 | length 807.8
  Top Layer w9: v1(1066.93,1425.2) 1153.54,1338.58 1153.54,1192.91 1202.75,1143.7 IC3.38
  Bottom Layer w9: K11.1 775.2,1425.2 v1(1066.93,1425.2)
NetIC3_39: IC3.39 K11.4 | length 805.8
  Top Layer w9: K11.4 815.42,1584.98 838.04,1562.35 870.04,1562.35 965.21,1562.35 1019.68,1507.87 1019.68,1279.53 1175.2,1124.02 IC3.39
NetIC3_41: IC3.41 K11.5 | length 680.2
  Top Layer w9: K11.5 887.4,1285.43 1088.18,1084.65 IC3.41
NetIC3_44: IC3.44 K10.1 | length 1058.5
  Top Layer w6: K10.1 K10.1@471.8,619.05 ; IC3.44@1255.89,1024.61 IC3.44
  Top Layer w9: K10.1 443.31,632.28 468.5,657.48 589.01,657.48 956.13,1024.61 IC3.44@1255.89,1024.61
NetIC3_45: IC3.45 K10.2 | length 885.6
  Top Layer w6: K10.2 554.21,601.46 K10.2@566.02,601.46
  Top Layer w9: K10.2@566.02,601.46 970.47,1005.91 IC3.45
NetIC3_46: IC3.46 K12.2 R21.1 | length 1806.9
  Top Layer w9: K12.2 998.43,880.31 1104.33,986.22 IC3.46
  Top Layer w27: R21.1 253.94,348.43 232.28,326.77 232.28,220.47 248.03,204.72 v1(716.54,204.72)
  Bottom Layer w20: v1(716.54,204.72) v1@722.28,210.46
  Bottom Layer w27: v1@722.28,210.46 762.43,210.46 K12.2
NetIC3_47: IC3.47 K12.4 R22.1 | length 1353.5
  Top Layer w9: K12.4 1098.43,930.43 1134.54,966.54 IC3.47
  Top Layer w27: R22.1 v1(653.17,347.43)
  Bottom Layer w6: K12.4@1098.43,424.43 K12.4
  Bottom Layer w27: v1@654.47,348.72 805.75,500 1044.88,500 K12.4
NetIC3_48: IC3.48 K12.3 | length 713.9
  Top Layer w9: K12.3 1148.17,396.21 1148.17,919.83 1175.2,946.85 IC3.48
NetK2_2: K2.2 RE1.2 RE1.5 | length 1546.4
  Top Layer w6: RE1.5@846.46,4181.1 RE1.5
  Top Layer w20: RE1.5@846.46,4181.1 851.97,4175.59 RE1.5@866.93,4175.59
  Top Layer w27: K2.2 783.46,3326.77 1141.73,3685.04 RE1.2 1141.73,3900.79 RE1.5@866.93,4175.59
  Bottom Layer w20: RE1.2@1141.73,3783.46 RE1.2
NetK3_2: K3.2 R2.2 R4.2 R9.1 R13.2 | length 2675.1
  Top Layer w6: R13.2 R13.2@2512.8,2814.96 ; R9.1@2834.65,2173.23 R9.1 ; R2.2@2842.52,3101.38 R2.2
  Top Layer w20: R4.2 R4.2@1824.39,2638.36
  Top Layer w27: R4.2@1824.39,2638.36 1856.55,2638.36 1891.41,2673.23 v1(1897.64,2673.23) ; R13.2@2512.8,2814.96 K3.2 ; R9.1@2834.65,2173.23 2795.28,2173.23 2767.72,2200.79 2767.72,2740.16 K3.2 ; R2.2@2842.52,3101.38 K3.2
  Bottom Layer w27: v1(1897.64,2673.23) 1897.64,2667 1942.55,2622.1 1942.55,2559.17 1985.97,2515.75 2543.31,2515.75 K3.2
NetK8_1: K8.1 L2.4 | length 720.8
  Top Layer w27: L2.4 2560.24,1249.21 2764.84,1453.82 2764.84,1650.67 K8.1
NetK8_2: K8.2 L2.3 | length 846.9
  Top Layer w27: L2.3 2610.17,1349.21 2732.28,1471.32 2732.28,1814.96 K8.2
NetL2_1: L2.1 T3.3 | length 272.2
  Top Layer w6: T3.3 T3.3@2830.91,988.39
  Top Layer w27: T3.3@2830.91,988.39 L2.1
NetR7_2: R7.2 R10.2 T1.2 | length 1145.4
  Top Layer w6: R10.2 R10.2@382.88,1909.45 ; R7.2 R7.2@385.83,2148.62
  Top Layer w20: T1.2 T1.2@365.15,2924.21 ; v1@437.99,2924.21 v1(440.94,2921.26)
  Top Layer w27: T1.2@365.15,2924.21 v1@437.99,2924.21 ; R10.2@382.88,1909.45 R7.2 ; R7.2@385.83,2148.62 385.83,2633.86 468.5,2716.54 v1(468.5,2783.46)
  Bottom Layer w20: v1@440.94,2913.14 v1(440.94,2921.26)
  Bottom Layer w27: v1@440.94,2913.14 468.5,2885.58 v1(468.5,2783.46)
NetR11_1: R11.1 R12.1 | length 227.7
  Top Layer w6: 2420.28,2253.36 2424.21,2249.43
  Top Layer w20: 2420.28,2253.36 2420.28,2145.67 R11.1
  Top Layer w27: 2420.28,2253.36 R12.1
NetR17_1: R17.1 T2.2 T4.1 T5.2 | length 1425.8
  Top Layer w6: T2.2@2539.37,263.78 T2.2
  Top Layer w20: T5.2@2304.13,245.08 T5.2 2301.18,250 2306.93,255.75 2318.49,255.75 2318.64,255.91
  Top Layer w27: T4.1 2043.31,476.38 v1(2129.92,389.76) ; T5.2@2303.43,245.08 2301.46,245.08 2300.2,243.81 2300.2,166.34 v1(2299.21,165.35) 2676.18,165.35 2780.51,269.68 R17.1 ; 2318.64,255.91 2376.65,255.91 2412.09,291.34 2511.81,291.34 T2.2@2539.37,263.78
  Bottom Layer w20: v1(2129.92,389.76) v1@2133.86,385.83
  Bottom Layer w27: v1@2133.86,385.83 2133.86,240.16 2204.72,169.29 2295.28,169.29 v1(2299.21,165.35)
NetR18_1: R18.1 T3.1 | length 348.4
  Top Layer w27: R18.1 2779.53,549.21 2790.63,560.32 2835.91,560.32 2858.27,582.68 2858.27,794.6 2852.08,800.79 T3.1
NetR18_2: R18.2 T2.3 T5.3 | length 549.6
  Top Layer w6: T2.3@2509.84,326.77 T2.3
  Top Layer w27: T5.3 T2.3@2509.84,326.77 ; T2.3@2516.03,334.93 2516.03,378.23 2664.09,526.3 2687.71,526.3 2698.82,537.4 R18.2
NetR19_1: R19.1 R20.2 T4.2 | length 859.8
  Top Layer w6: R20.2 R20.2@2036.42,269.68 ; R19.1 R19.1@2463.58,563.98
  Top Layer w20: R19.1@2448.97,562.84 2448.97,553.98 R19.1
  Top Layer w27: R20.2@2036.42,269.68 2003.94,302.17 2003.94,586.27 2019.75,602.08 2041.06,602.08 T4.2 2407.48,604.33 R19.1@2448.97,562.84
"PC0 CPU": IC3.10 R19.2 | length 1531.7
  Top Layer w6: v1(2506.81,444.09) v1@2506.81,451.81
  Top Layer w9: v1(1490.16,516.43) IC3.10 ; v1@2506.81,451.81 2544.29,489.3 R19.2
  Bottom Layer w9: v1(1490.16,516.43) 1562.49,444.09 v1(2506.81,444.09)
"PD0 CPU": C6.2 IC3.20 R5.1 | length 974.1
  Top Layer w6: R5.1@1720.44,1919.26 R5.1
  Top Layer w9: IC3.20 1686.21,1084.65 1740.16,1138.59 1740.16,1700.75 C6.2
  Top Layer w20: C6.2 R5.1@1720.44,1919.26
"PD1 CPU": C12.2 IC3.21 R14.2 | length 1477.8
  Top Layer w6: R14.2@2417.29,1922.21 R14.2
  Top Layer w9: IC3.21 1649.08,1104.33 1704.72,1159.97 v1(1704.72,1448.82) ; v1@2316.93,1710.63 C12.2@2415.32,1710.63
  Top Layer w20: v1(2314.96,1712.6) v1@2316.93,1710.63 ; C12.2@2415.32,1710.63 C12.2
  Top Layer w27: C12.2 R14.2@2417.29,1922.21
  Bottom Layer w9: v1(1704.72,1448.82) 1787.4,1531.5 2133.86,1531.5 v1(2314.96,1712.6)
"PD2 CPU": D2.1 IC3.22 R3.1 R6.2 | length 2847.1
  Top Layer w6: D2.1@1170.67,2915.43 D2.1 ; R3.1@1673.16,3091.98 1673.28,3091.98 R3.1
  Top Layer w9: D2.1@1170.67,2915.43 1264.17,2915.43 1667.17,2512.43 1667.17,1147.43 1643.77,1124.02 IC3.22
  Top Layer w27: D2.1 1170.67,2973.82 1348.42,3151.57 R6.2 1572.84,3151.57 1646.49,3077.92 1696.69,3077.92 R3.1
"PE0 CPU": IC3.30 R7.1 | length 2750.4
  Top Layer w6: R7.1 R7.1@307.09,2140.75 ; v1@954.19,2552.61 v1(960.63,2559.06)
  Top Layer w9: v1(1055.12,2559.06) 1173.23,2559.06 1218.17,2514.11 1218.17,2061.43 1442.13,1837.47 1442.13,1563.43 1431.1,1552.4 IC3.30
  Top Layer w20: R7.1@295.28,2128.94 R7.1@307.09,2140.75 ; v1(326.77,2055.12) v1@326.77,2063.24 ; v1(531.5,2102.36) v1@531.5,2110.48
  Top Layer w27: R7.1@295.28,2128.94 295.28,2094.73 v1@326.77,2063.24 ; v1@531.5,2110.48 562.99,2141.98 562.99,2354.33 761.28,2552.61 v1@954.19,2552.61
  Bottom Layer w20: v1@531.25,2102.36 v1(531.5,2102.36)
  Bottom Layer w27: v1(326.77,2055.12) 484.01,2055.12 v1@531.25,2102.36 ; v1(960.63,2559.06) v1(1055.12,2559.06)
VIN: B1.1 C1.2 R3.2 R17.2 T2.1 T3.2 | length 6768.1
  Top Layer w6: R3.2@1675.17,3154.53 R3.2 ; T2.1 T2.1@2478.35,251.97
  Top Layer w20: B1.1 1787.24,3929.29 B1.1@1787.24,3921.53 ; T2.1@2478.35,251.97 2482.13,248.19 T2.1@2482.13,244.25 ; T3.2@2579.72,890.55 T3.2 T3.2@2642.1,977.54 ; R17.2 2714.41,290.2 R17.2@2714.41,301.02
  Top Layer w27: R3.2 1700.79,3232.28 1587.17,3345.91 1587.17,3850.94 1685.04,3948.82 B1.1 1767.72,3885.83 v1(1814.96,3838.58) ; T2.1@2482.13,244.25 2517.72,208.66 2586.61,208.66 2650.51,272.56 2696.77,272.56 R17.2 2699.8,333.66 2968.5,602.36 2968.5,791.34 2869.29,890.55 T3.2@2579.72,890.55 ; T3.2@2642.1,977.54 2642.1,1020.06 2704.72,1082.68 v1(2771.65,1082.68) ; v1(2889.76,1078.74) 2992.13,1078.74 3038.96,1125.57 3038.96,3276 v1(2944.88,3370.08)
  Bottom Layer w20: C1.2@2444.88,3578.74 C1.2 C1.2@2456.69,3547.24 ; v1(2771.65,1082.68) v1@2773.62,1080.71 ; v1@2887.8,1080.71 v1(2889.76,1078.74)
  Bottom Layer w27: v1(1814.96,3838.58) 1881.89,3771.65 2251.97,3771.65 C1.2@2444.88,3578.74 ; C1.2@2456.69,3547.24 2767.72,3547.24 v1(2944.88,3370.08) ; v1@2773.62,1080.71 v1@2887.8,1080.71
pads on no net: IC3.4 IC3.5 IC3.6 IC3.7 IC3.8 IC3.9 IC3.12 IC3.13 IC3.18 IC3.19 IC3.36 IC3.37 K12.6 K12.8 RE1.4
